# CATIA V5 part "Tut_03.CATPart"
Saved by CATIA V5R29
Part number: Part1
Bounding box of the stored display mesh (mm): x -75 to 75, y 0 to 300, z 0 to 189
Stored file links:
  C:\Users\CADCIM 00\Desktop\catia parts file\C05\Tut_03.CATPart
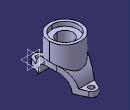
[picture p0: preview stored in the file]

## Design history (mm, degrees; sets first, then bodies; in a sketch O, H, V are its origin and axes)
Body1 (main body)
  Sketch1 on yz-plane, origin (0, 0, 0), H (0, 1, 0), V (0, 0, 1)
    arc A1 centre (150, 0) radius 105 from (251.9804, 25) to (48.0196, 25) ccw
    point P1 (150, 0)
    arc A2 centre (150, 0) radius 80 from (230, 0) to (70, 0) ccw
    point P2 (70, 0)
    line L1 (70, 0) -> (0, 0)
    line L2 (0, 0) -> (0, 25)
    line L3 (0, 25) -> (48.0196, 25)
    point P5 (251.9804, 25)
    line L4 (251.9804, 25) -> (300, 25)
    line L5 (300, 25) -> (300, 0)
    point P7 (300, 0)
    line L6 (300, 0) -> (230, 0)
    distance V P1 = 150
    radius A2 = 80
    radius A1 = 105
    distance L2 L5 = 300
    distance L4 L6 = 25
    coincidence: P1 H, P2 H, P5 L3, P7 H
    horizontal: L1 H, L3 H, L4 H, L6 H
    vertical: L2 V, L5 V
  Pad1: profile Sketch1, direction (1, 0, 0), length 75, mirrored extent
  Sketch2 on xy-plane, origin (0, 0, 0), H (1, 0, 0), V (0, 1, 0)
    arc A1 centre (0, 150) radius 75 from (-68.7386, 180) to (-68.7386, 120) ccw
    point P1 (0, 150)
    arc A2 centre (0, 275) radius 25 from (22.9129, 285) to (-22.9129, 285) ccw
    point P2 (0, 275)
    arc A3 centre (0, 25) radius 25 from (-22.9129, 15) to (22.9129, 15) ccw
    point P3 (0, 25)
    line L1 (-68.7386, 180) -> (-22.9129, 285)
    line L2 (22.9129, 15) -> (68.7386, 120)
    point P7 (68.7386, 120)
    line L3 (-22.9129, 15) -> (-68.7386, 120)
    line L4 (68.7386, 180) -> (22.9129, 285)
    reference projected line E1 (-75, 300) -> (75, 300) from edge [face of Pad1 from Sketch1.L4 | face of Pad1 from Sketch1.L5]
    reference projected line E2 (-75, 0) -> (75, 0) from edge [face of Pad1 from Sketch1.L2 | face of Pad1 from Sketch1.L3]
    reference projected line E3 (-75, 251.9804) -> (-75, 48.0196) from edge [start face of Pad1 | face of Pad1 from Sketch1.A1]
    reference projected line E4 (75, 251.9804) -> (75, 48.0196) from edge [face of Pad1 from Sketch1.A1 | end face of Pad1]
    arc A4 centre (0, 150) radius 75 from (68.7386, 120) to (68.7386, 180) ccw
    reference projected line E5 (-75, 300) -> (75, 300) from edge [face of Pad1 from Sketch1.L4 | face of Pad1 from Sketch1.L5]
    radius A2 = 25
    distance E5 P1 = 150
    coincidence: P1 V, P2 V, P3 V, A3 O, A1 P7, A1 A4
    tangency: L1 A1, L1 A2, L2 A3, L2 A1, L3 A3, L3 A1, L4 A1, L4 A2, A2 E1, A3 E2, A1 E3, A1 E4
    equal size: A2 A3
  Pocket1: profile Sketch2, direction (0, 0, 1), through (limit type 3), outer side
  Plane1: type Offset, RefPlane xy-plane, Offset 189
  Sketch3 on Plane1, origin (0, 0, 189), H (1, 0, 0), V (0, 1, 0)
    circle A1 centre (0, 150) radius 75
    point P1 (0, 150)
    reference projected arc E1 centre (0, 150) radius 74.9999 from (68.7386, 120) to (68.7386, 180) ccw from edge [face of Pocket1 | face of Pad1 from Sketch1.A1]
    radius A1 = 75
    coincidence: P1 V
    tangency: A1 E1
  Pad2: profile Sketch3, direction (0, 0, 1), up to face of Pad1 from Sketch1.A1
  Sketch4 on yz-plane, origin (0, 0, 0), H (0, 1, 0), V (0, 0, 1)
    line L1 (150, 189) -> (150, 29.7437)
    line L2 (150, 29.7437) -> (187.5, 29.7437)
    line L3 (187.5, 29.7437) -> (187.5, 169)
    line L4 (187.5, 169) -> (211.5, 169)
    line L5 (211.5, 169) -> (211.5, 189)
    line L6 (211.5, 189) -> (150, 189)
    reference projected line E1 (75, 189) -> (225, 189) from edge [face of Pad2 from Sketch3.A1 | start face of Pad2]
    axis line L7 (150, 8.3283) -> (150, 223.7015)
    point P7 (150, 8.3283)
    distance L7 V = 150
    length L5 = 20
    radius about axis L3 L7 = 37.5
    radius about axis L5 L7 = 61.5
    vertical: L1 V, L3 V, L5 V, L7 V
    horizontal: L2 H, L4 H, L6 H
    coincidence: L6 E1, P7 L1
  Groove1: profile Sketch4, axis Sketch4.L7, angle 360
  Sketch5 on face of Pad1 from Sketch1.L4, origin (0, 0, 25), H (1, 0, 0), V (0, 1, 0)
    circle A1 centre (0, 275) radius 12.5
    point P1 (0, 275)
    reference projected arc E1 centre (0, 275) radius 25 from (22.9129, 285) to (-22.9129, 285) ccw from edge [face of Pad1 from Sketch1.L4 | face of Pocket1]
    circle A2 centre (0, 25) radius 12.5
    point P2 (0, 25)
    reference projected arc E2 centre (0, 25) radius 25 from (-22.9129, 15) to (22.9129, 15) ccw from edge [face of Pad1 from Sketch1.L3 | face of Pocket1]
    radius A1 = 12.5
    coincidence: P1 V, P2 V
    concentricity: A1 E1, A2 E2
    equal size: A1 A2
  Pocket2: profile Sketch5, direction (0, 0, -1), through (limit type 3)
